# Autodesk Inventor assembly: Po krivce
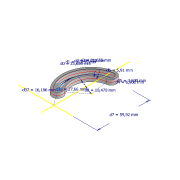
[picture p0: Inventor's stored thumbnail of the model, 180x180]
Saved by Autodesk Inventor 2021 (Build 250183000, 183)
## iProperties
Created: 2023-12
Part Number: Po krivce
Document SubType Name: Assembly
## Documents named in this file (3)
- D:\SkolaV\Strojar\Polytechnika\Napady\Hlavolam vzor SPS Hronov\a\CAD\Po krivce.iam
- D:\SkolaV\Strojar\Polytechnika\Napady\Hlavolam vzor SPS Hronov\a\CAD\Kulicka.ipt
- D:\SkolaV\Strojar\Polytechnika\Napady\Hlavolam vzor SPS Hronov\a\CAD\Oblouk.ipt
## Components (2 placed, 2 different names)
1. Kulicka:1 — Proti sobě:1, Proti sobě:2, Přechodová:1
2. Oblouk:1 — Proti sobě:1, Proti sobě:2, Přechodová:1
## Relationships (3: Mate 2, Transitional 1)
- Proti sobě:1 [Mate]: Kulicka:1 ↔ Oblouk:1
- Proti sobě:2 [Mate]: Kulicka:1 ↔ Oblouk:1
- Přechodová:1 [Transitional]: Kulicka:1 ↔ Oblouk:1
